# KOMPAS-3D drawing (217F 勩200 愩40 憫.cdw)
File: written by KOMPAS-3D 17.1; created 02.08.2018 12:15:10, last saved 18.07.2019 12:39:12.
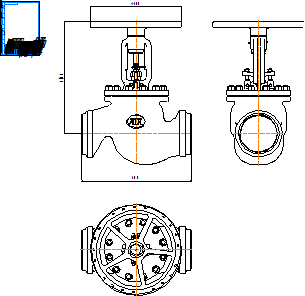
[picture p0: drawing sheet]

Sheet 1: A4, portrait

Title block, sheet 1: name: 217F Ду200 Ру40 СС; material: Внимание! Данный продукт является объектом авторского права ООО «Торговый Дом АДЛ». / Запрещается изменение, копирование, распространение / (в том числе путем копирования на другие сайты и ресурсы в Интернете) / или любое иное использование информации и объектов без предварительного / согласия правообладателя (ООО «Торговый Дом АДЛ»).; sheets: 1; organisation: ООО "Торговый дом АДЛ"; sheet format: A4; stored path: \\adlc.lan\data\АДЛ_ПКД\3D-модели\Поставщики\Zetkama\Вентили\217F\KOMPAS 2D\217F Ду200 Ру40 СС.cdw

Views: Вид 1, Проекционный вид 2, Проекционный вид 3
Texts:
  kka
  adl
Dimensions and other numbers on the sheet: 600; 613,2; 500; 1:1; 1; 217F Ду200 Ру40 СС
